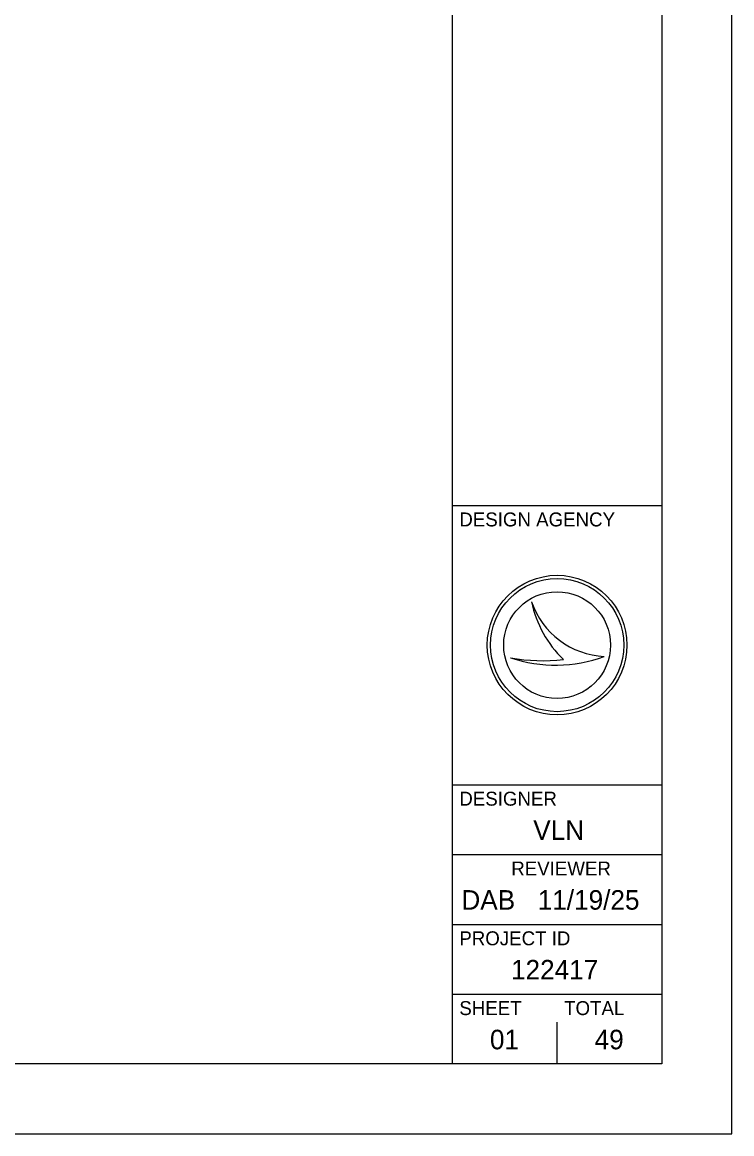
# Model space of a CAD drawing. Extents: x 0 to 42.4, y 0 to 22.
# Drawn here: x 28.92 to 34, y 0 to 7.96 of the extents above; entities that cross this region are included whole.
import ezdxf

# ---------------------------------------------------------------- set-up
doc = ezdxf.new("R2010")
doc.units = 0
for name, color, linetype in [('SH_Border', 7, 'Continuous'), ('SH_Cut_Line', 7, 'Continuous'), ('SH_Data', 7, 'Continuous')]:
    doc.layers.add(name, color=color, linetype=linetype)

msp = doc.modelspace()

# ---------------------------------------------------------------- linework, layer by layer
at = {"layer": 'SH_Border'}
for p, q in [((32, 0.5), (32, 21.5)), ((32, 4.5), (33.5, 4.5)), ((32, 2.5), (33.5, 2.5)), ((32, 2), (33.5, 2)), ((32, 1.5), (33.5, 1.5)), ((32, 1), (33.5, 1))]:
    msp.add_line(p, q, dxfattribs=at)
msp.add_lwpolyline([(1.5, 21.5), (33.5, 21.5), (33.5, 0.5), (1.5, 0.5)], close=True, dxfattribs=at)
at = {"layer": 'SH_Cut_Line'}
msp.add_lwpolyline([(0, 0), (34, 0), (34, 22), (0, 22)], close=True, dxfattribs=at)
at = {"layer": 'SH_Data'}
for p, q in [((32.5674, 3.8096), (32.5675, 3.8096)), ((32.75, 3.5), (32.75, 3.5)), ((32.4172, 3.4095), (32.4172, 3.4095)), ((33.0873, 3.4185), (33.0873, 3.4185)), ((32.75, 0.5), (32.75, 0.8)), ((32.375, 0.675), (32.375, 0.675))]:
    msp.add_line(p, q, dxfattribs=at)
for radius in [0.5, 0.4768, 0.4768, 0.3822]:
    msp.add_circle((32.75, 3.5), radius, dxfattribs=at)
for centre, radius, start, end in [((33.1159, 3.9976), 0.5798, 198.92567, 198.93195), ((33.3467, 3.9701), 0.7956, 191.63793, 191.64215), ((33.1159, 3.9976), 0.5798, 198.93195, 267.16574), ((33.3467, 3.9701), 0.7956, 191.64215, 226.09467), ((32.7394, 4.37), 1.0131, 251.45764, 290.08324), ((32.648, 4.6543), 1.2661, 259.49639, 259.49952), ((32.7394, 4.37), 1.0131, 251.45274, 251.45764), ((32.648, 4.6543), 1.2661, 259.49952, 276.66723)]:
    msp.add_arc(centre, radius, start, end, dxfattribs=at)

# ---------------------------------------------------------------- texts
for s, height, p in [('DESIGN AGENCY', 0.1, (32.05, 4.35)), ('DESIGNER', 0.1, (32.05, 2.35)), ('VLN', 0.14, (32.5792, 2.105)), ('REVIEWER', 0.1, (32.4218, 1.85)), ('11/19/25', 0.14, (32.611, 1.605)), ('DAB', 0.14, (32.0648, 1.605)), ('PROJECT ID', 0.1, (32.05, 1.35)), ('122417', 0.14, (32.4198, 1.105)), ('SHEET', 0.1, (32.05, 0.85)), ('TOTAL', 0.1, (32.8, 0.85)), ('01', 0.14, (32.2692, 0.605)), ('49', 0.14, (33.0188, 0.605))]:
    msp.add_text(s, height=height, dxfattribs=at).set_placement(p)

doc.saveas('drawing.dxf')
